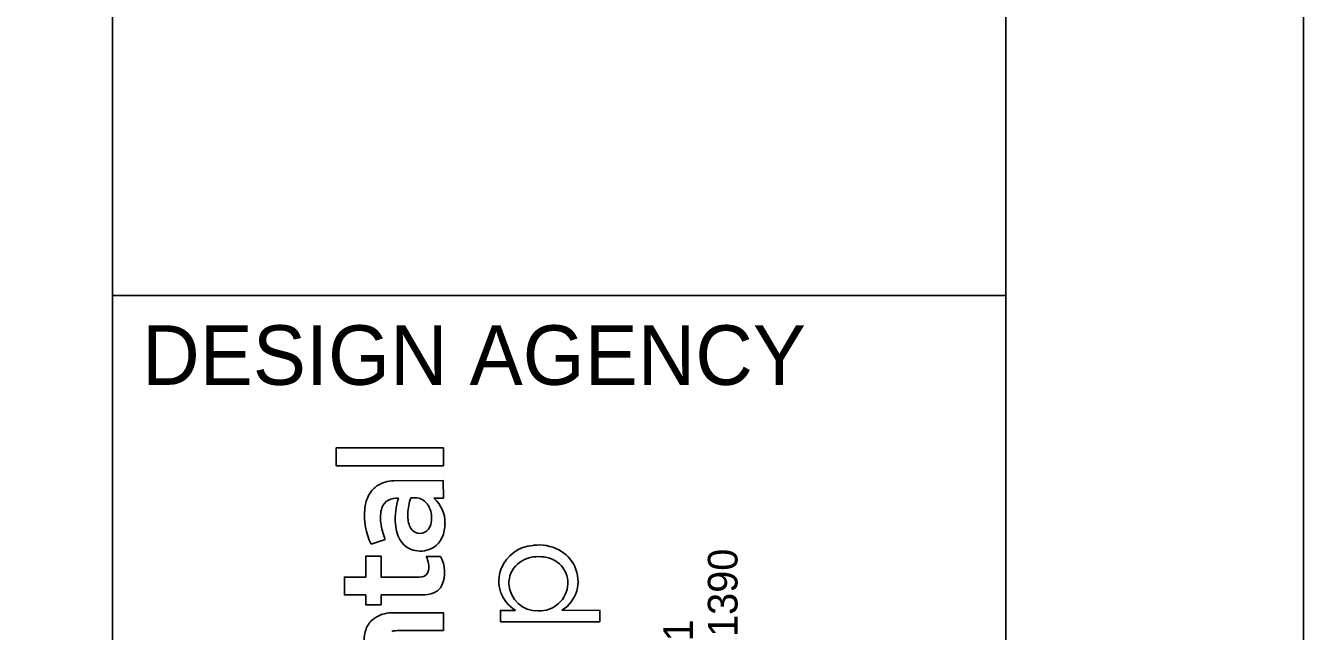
# Model space of a CAD drawing. Extents: x -0.3 to 34, y 0 to 22.
# Drawn here: x 31.854 to 34, y 3.936 to 4.953 of the extents above; entities that cross this region are included whole.
import ezdxf

# ---------------------------------------------------------------- set-up
doc = ezdxf.new("R2010")
doc.units = 0
for name, color, linetype in [('SH_Border', 7, 'Continuous'), ('SH_Cut_Line', 7, 'Continuous'), ('SH_Data', 7, 'Continuous')]:
    doc.layers.add(name, color=color, linetype=linetype)

msp = doc.modelspace()

# ---------------------------------------------------------------- linework, layer by layer
at = {"layer": 'SH_Border'}
for p, q in [((32, 0.5), (32, 21.5)), ((32, 4.5), (33.5, 4.5))]:
    msp.add_line(p, q, dxfattribs=at)
msp.add_lwpolyline([(1.5, 21.5), (33.5, 21.5), (33.5, 0.5), (1.5, 0.5)], close=True, dxfattribs=at)
at = {"layer": 'SH_Cut_Line'}
msp.add_lwpolyline([(0, 0), (34, 0), (34, 22), (0, 22)], close=True, dxfattribs=at)
at = {"layer": 'SH_Data'}
for p, q in [((32.3756, 4.2141), (32.3756, 4.244)), ((32.3756, 4.244), (32.5557, 4.244)), ((32.5557, 4.244), (32.5557, 4.2141)), ((32.5557, 4.2141), (32.3756, 4.2141)), ((32.4727, 4.189), (32.5555, 4.1892)), ((32.5555, 4.1892), (32.5557, 4.1596)), ((32.5557, 4.1596), (32.5397, 4.1596)), ((32.4582, 4.0904), (32.4343, 4.0823)), ((32.4254, 4.027), (32.4255, 4.0621)), ((32.4255, 4.0621), (32.4511, 4.0621)), ((32.4511, 4.0621), (32.4512, 4.027)), ((32.527, 4.0616), (32.5511, 4.0616)), ((32.3896, 3.9972), (32.3896, 4.027)), ((32.3896, 4.027), (32.4254, 4.027)), ((32.4512, 4.027), (32.515, 4.027)), ((32.515, 4.027), (32.52, 4.0275)), ((32.4254, 3.9972), (32.3896, 3.9972)), ((32.4254, 3.9807), (32.4254, 3.9972)), ((32.5197, 3.9972), (32.4511, 3.9972)), ((32.4511, 3.9972), (32.4511, 3.9807)), ((32.4511, 3.9807), (32.4254, 3.9807)), ((32.6515, 3.9521), (32.6515, 3.9711)), ((32.6515, 3.9711), (32.6771, 3.9711)), ((32.7549, 3.9713), (32.8186, 3.9711)), ((32.8186, 3.9711), (32.8184, 3.9521)), ((32.4644, 3.9669), (32.4729, 3.9673)), ((32.4729, 3.9673), (32.5557, 3.9673)), ((32.5557, 3.9673), (32.5557, 3.9375)), ((32.8184, 3.9521), (32.6515, 3.9521)), ((32.5557, 3.9375), (32.4814, 3.9375))]:
    msp.add_line(p, q, dxfattribs=at)
msp.add_lwpolyline([(32.3756, 4.2141), (32.3756, 4.244), (32.5557, 4.244), (32.5557, 4.2141)], close=True, dxfattribs=at)
for points in [[(32.4727, 4.189), (32.5555, 4.1892), (32.5557, 4.1596)], [(32.5557, 4.1596), (32.5397, 4.1596)], [(32.4582, 4.0904), (32.4343, 4.0823)], [(32.5197, 3.9972), (32.4511, 3.9972), (32.4511, 3.9807), (32.4254, 3.9807), (32.4254, 3.9972), (32.3896, 3.9972), (32.3896, 4.027), (32.4254, 4.027), (32.4255, 4.0621), (32.4511, 4.0621), (32.4512, 4.027), (32.515, 4.027), (32.52, 4.0275)], [(32.527, 4.0616), (32.5511, 4.0616)], [(32.7549, 3.9713), (32.8186, 3.9711), (32.8184, 3.9521), (32.6515, 3.9521)], [(32.6515, 3.9521), (32.6515, 3.9711), (32.6771, 3.9711)], [(32.4644, 3.9669), (32.4729, 3.9673), (32.5557, 3.9673), (32.5557, 3.9375), (32.4814, 3.9375)]]:
    msp.add_lwpolyline(points, dxfattribs=at)
for centre, radius, start, end in [((32.4745, 4.1326), 0.0565, 91.8942, 122.6317), ((32.4745, 4.1326), 0.0565, 91.8942, 122.6317), ((32.4685, 4.1447), 0.043, 124.537, 155.6594), ((32.4685, 4.1447), 0.043, 124.537, 155.6594), ((32.4882, 4.1361), 0.0646, 155.9764, 175.3149), ((32.4882, 4.1361), 0.0646, 155.9764, 175.3149), ((32.5076, 4.1265), 0.0576, 163.1369, 188.1675), ((32.5076, 4.1265), 0.0576, 163.1369, 188.1675), ((32.4753, 4.1356), 0.024, 119.4252, 161.6629), ((32.4753, 4.1356), 0.024, 119.4252, 161.6629), ((32.4779, 4.1278), 0.0321, 85.3802, 116.6222), ((32.4779, 4.1278), 0.0321, 85.3802, 116.6222), ((32.5879, 4.1251), 0.1129, 162.0821, 184.5285), ((32.5879, 4.1251), 0.1129, 162.0821, 184.5285), ((32.5801, 4.1313), 0.0841, 159.8366, 178.0362), ((32.5801, 4.1313), 0.0841, 159.8366, 178.0362), ((32.5051, 4.1074), 0.053, 79.6696, 94.2322), ((32.5051, 4.1074), 0.053, 79.6696, 94.2322), ((32.5089, 4.1364), 0.0238, 56.8913, 76.2149), ((32.5089, 4.1364), 0.0238, 56.8913, 76.2149), ((32.5052, 4.1318), 0.0297, 17.5984, 55.7282), ((32.5052, 4.1318), 0.0297, 17.5984, 55.7282), ((32.5055, 4.1191), 0.0529, 358.0746, 49.762), ((32.5055, 4.1191), 0.0529, 358.0746, 49.762), ((32.5364, 4.1308), 0.113, 174.6101, 205.3899), ((32.5364, 4.1308), 0.113, 174.6101, 205.3899), ((32.5466, 4.1303), 0.0506, 175.5903, 199.8857), ((32.5466, 4.1303), 0.0506, 175.5903, 199.8857), ((32.4916, 4.1264), 0.0443, 345.9408, 18.9919), ((32.4916, 4.1264), 0.0443, 345.9408, 18.9919), ((32.5473, 4.1297), 0.0973, 186.7598, 203.7981), ((32.5473, 4.1297), 0.0973, 186.7598, 203.7981), ((32.5328, 4.1187), 0.0575, 182.5676, 213.7144), ((32.5328, 4.1187), 0.0575, 182.5676, 213.7144), ((32.5164, 4.1189), 0.0184, 198.2844, 293.3081), ((32.5164, 4.1189), 0.0184, 198.2844, 293.3081), ((32.5152, 4.1199), 0.0199, 295.2883, 347.4639), ((32.5152, 4.1199), 0.0199, 295.2883, 347.4639), ((32.5019, 4.1168), 0.0566, 336.016, 0.5951), ((32.5019, 4.1168), 0.0566, 336.016, 0.5951), ((32.5149, 4.1078), 0.0366, 215.0668, 259.8133), ((32.5149, 4.1078), 0.0366, 215.0668, 259.8133), ((32.5175, 4.1097), 0.0394, 303.4436, 336.18), ((32.5175, 4.1097), 0.0394, 303.4436, 336.18), ((32.7108, 4.0182), 0.0624, 93.9866, 158.3119), ((32.7108, 4.0182), 0.0624, 93.9866, 158.3119), ((32.7156, 4.0065), 0.0746, 62.6889, 97.0135), ((32.7156, 4.0065), 0.0746, 62.6889, 97.0135), ((32.5175, 4.1131), 0.0423, 257.5256, 300.882), ((32.5175, 4.1131), 0.0423, 257.5256, 300.882), ((32.4863, 4.042), 0.0452, 10.1545, 25.723), ((32.4863, 4.042), 0.0452, 10.1545, 25.723), ((32.503, 4.0351), 0.0549, 336.589, 28.8991), ((32.503, 4.0351), 0.0549, 336.589, 28.8991), ((32.7138, 4.0102), 0.0513, 87.8965, 131.1812), ((32.7138, 4.0102), 0.0513, 87.8965, 131.1812), ((32.7175, 4.0102), 0.0513, 49.9089, 92.0363), ((32.7175, 4.0102), 0.0513, 49.9089, 92.0363), ((32.7212, 4.0191), 0.0608, 25.0657, 61.9602), ((32.7212, 4.0191), 0.0608, 25.0657, 61.9602), ((32.5184, 4.04), 0.0126, 277.6142, 353.7918), ((32.5184, 4.04), 0.0126, 277.6142, 353.7918), ((32.4957, 4.0436), 0.0356, 351.914, 10.2059), ((32.4957, 4.0436), 0.0356, 351.914, 10.2059), ((32.707, 4.0202), 0.0581, 158.656, 198.171), ((32.707, 4.0202), 0.0581, 158.656, 198.171), ((32.7092, 4.0167), 0.0434, 132.3289, 182.0949), ((32.7092, 4.0167), 0.0434, 132.3289, 182.0949), ((32.7215, 4.0173), 0.0433, 358.0487, 47.9447), ((32.7215, 4.0173), 0.0433, 358.0487, 47.9447), ((32.7245, 4.02), 0.0574, 301.9776, 25.6418), ((32.7245, 4.02), 0.0574, 301.9776, 25.6418), ((32.5291, 4.0261), 0.0275, 292.6889, 332.0598), ((32.5291, 4.0261), 0.0275, 292.6889, 332.0598), ((32.7135, 4.0181), 0.0478, 183.5974, 271.7045), ((32.7135, 4.0181), 0.0478, 183.5974, 271.7045), ((32.7172, 4.018), 0.0477, 267.3149, 357.4019), ((32.7172, 4.018), 0.0477, 267.3149, 357.4019), ((32.5209, 4.0486), 0.0514, 268.6727, 291.5235), ((32.5209, 4.0486), 0.0514, 268.6727, 291.5235), ((32.7103, 4.0243), 0.0627, 200.8399, 238.0162), ((32.7103, 4.0243), 0.0627, 200.8399, 238.0162), ((32.4635, 3.9255), 0.0402, 132.2238, 161.6823), ((32.4635, 3.9255), 0.0402, 132.2238, 161.6823), ((32.4687, 3.9172), 0.0499, 94.9706, 130.2248), ((32.4687, 3.9172), 0.0499, 94.9706, 130.2248), ((32.4787, 3.9211), 0.056, 162.274, 187.7917), ((32.4787, 3.9211), 0.056, 162.274, 187.7917), ((32.4811, 3.8915), 0.046, 89.6051, 105.3303), ((32.4811, 3.8915), 0.046, 89.6051, 105.3303)]:
    msp.add_arc(centre, radius, start, end, dxfattribs=at)

# ---------------------------------------------------------------- texts
msp.add_text('DESIGN AGENCY', height=0.1, dxfattribs=at).set_placement((32.05, 4.35))
for s, p in [('800.835.1390', (33.0497, 3.6671)), ('450 GRANT ST., AKRON, OH  44311', (32.9749, 2.8374))]:
    msp.add_text(s, height=0.049846, rotation=90, dxfattribs=at).set_placement(p)

doc.saveas('drawing.dxf')
